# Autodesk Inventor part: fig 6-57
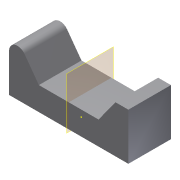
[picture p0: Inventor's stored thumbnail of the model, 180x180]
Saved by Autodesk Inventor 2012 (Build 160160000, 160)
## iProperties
Created: 2011-07
Part Number: fig 6-57
Material: Default
Document SubType Name: Modeling
Designer: CadCim
Density: 1 g/cm^3
Author: CadCim
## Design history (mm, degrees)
sketch "Sketch1"
  geometry: 1 further point
sketch "Sketch2"
  geometry: L1 (3, -4)-(17, -4); L2 (17, -4)-(17, 7); L3 (17, 7)-(14, 7); L4 (14, 7)-(10, 1.5); L5 (10, 1.5)-(3, 1.5); L6 (3, -4)-(-11, -4); L7 (-11, -4)-(-11, 7); L8 (-11, 7)-(-8, 7); L9 (-8, 7)-(-4, 1.5); L10 (-4, 1.5)-(3, 1.5); 1 further point
  constraints: 20 end point, 2 parallel, 1 perpendicular
extrude "Extrusion1" new body sketch "Sketch2" distance "d0" = 10; taper "d1" = 0 deg
fillet "Fillet1" dims "d2" = 2
workplane "Work Plane1"
body "Solid1"
